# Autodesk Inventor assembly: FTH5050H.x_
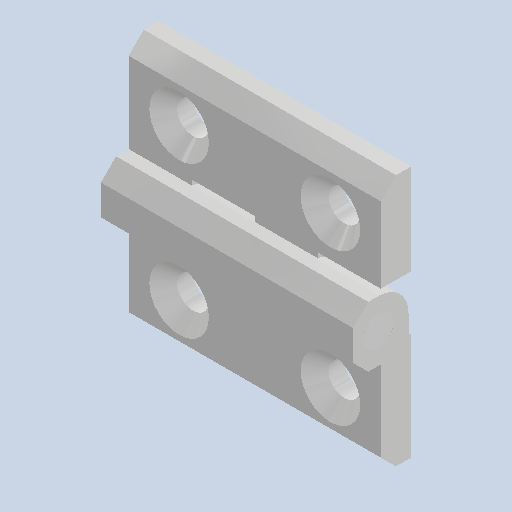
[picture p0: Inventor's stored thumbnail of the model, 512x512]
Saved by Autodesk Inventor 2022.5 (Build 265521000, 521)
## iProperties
Created: 2024-08
Part Number: FTH5050H.x_
Document SubType Name: Assembly
Designer: ImaoCorp
Author: ImaoCorp
Sending System: SOLIDWORKS 2022-2022290
MC: AMD64
MC_MODEL: Intel64 Family 6 Model 60 Stepping 3, GenuineIntel
OS: Windows_NT
FRU: Parasolid Version 33.1, build 260,  4-25-2022
FORMAT: text
GUISE: transmit
KEY: FILEFTH5050H.x_t
DATE: Mon Aug  5 14:46:33 2024
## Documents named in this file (4)
- Y:\5.更新分\2024年対応\0805_FTH\fth5050h\FTH5050H.x_.iam
- Y:\5.更新分\2024年対応\0805_FTH\fth5050h\FTH5050H_01.ipt
- Y:\5.更新分\2024年対応\0805_FTH\fth5050h\FTH5050H_02.ipt
- Y:\5.更新分\2024年対応\0805_FTH\fth5050h\FTH5050H_03.ipt
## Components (3 placed, 3 different names)
1. FTH5050H_01
2. FTH5050H_02
3. FTH5050H_03
